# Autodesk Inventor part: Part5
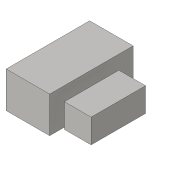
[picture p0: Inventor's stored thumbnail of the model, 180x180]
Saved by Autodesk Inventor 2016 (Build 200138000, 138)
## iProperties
Created: 2015-07
Part Number: Part5
Material: Generic
Document SubType Name: Modeling
Designer: Sandeep
Density: 1 g/cm^3
Appearance: Default
Author: Sandeep
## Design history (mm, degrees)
sketch "Sketch1"
  geometry: L1 (-7.411, 3.941)-(-1.385, 3.941); L2 (-1.385, 3.941)-(-1.385, -7.628); L3 (-1.385, -7.628)-(-7.411, -7.628); L4 (-7.411, -7.628)-(-7.411, 3.941); 1 further point
  constraints: 8 end point, 2 parallel, 1 horizontal, 1 perpendicular
extrude "Extrusion1" new body sketch "Sketch1" distance "d0" = 5; taper "d1" = 0 deg
sketch "Sketch2"
  geometry: L1 (1.52, -7.467)-(7.078, -7.467); L2 (7.078, -7.467)-(7.078, 3.854); L3 (7.078, 3.854)-(1.52, 3.854); L4 (1.52, 3.854)-(1.52, -7.467); 1 further point
  constraints: 8 end point, 2 parallel, 1 horizontal, 1 perpendicular
extrude "Extrusion2" new body sketch "Sketch2" distance "d2" = 5; taper "d3" = 0 deg
node "Direct Edit1"
body "Solid1"
body "Solid2"
feature "Scale1"
other parameters: "d4" = 15
